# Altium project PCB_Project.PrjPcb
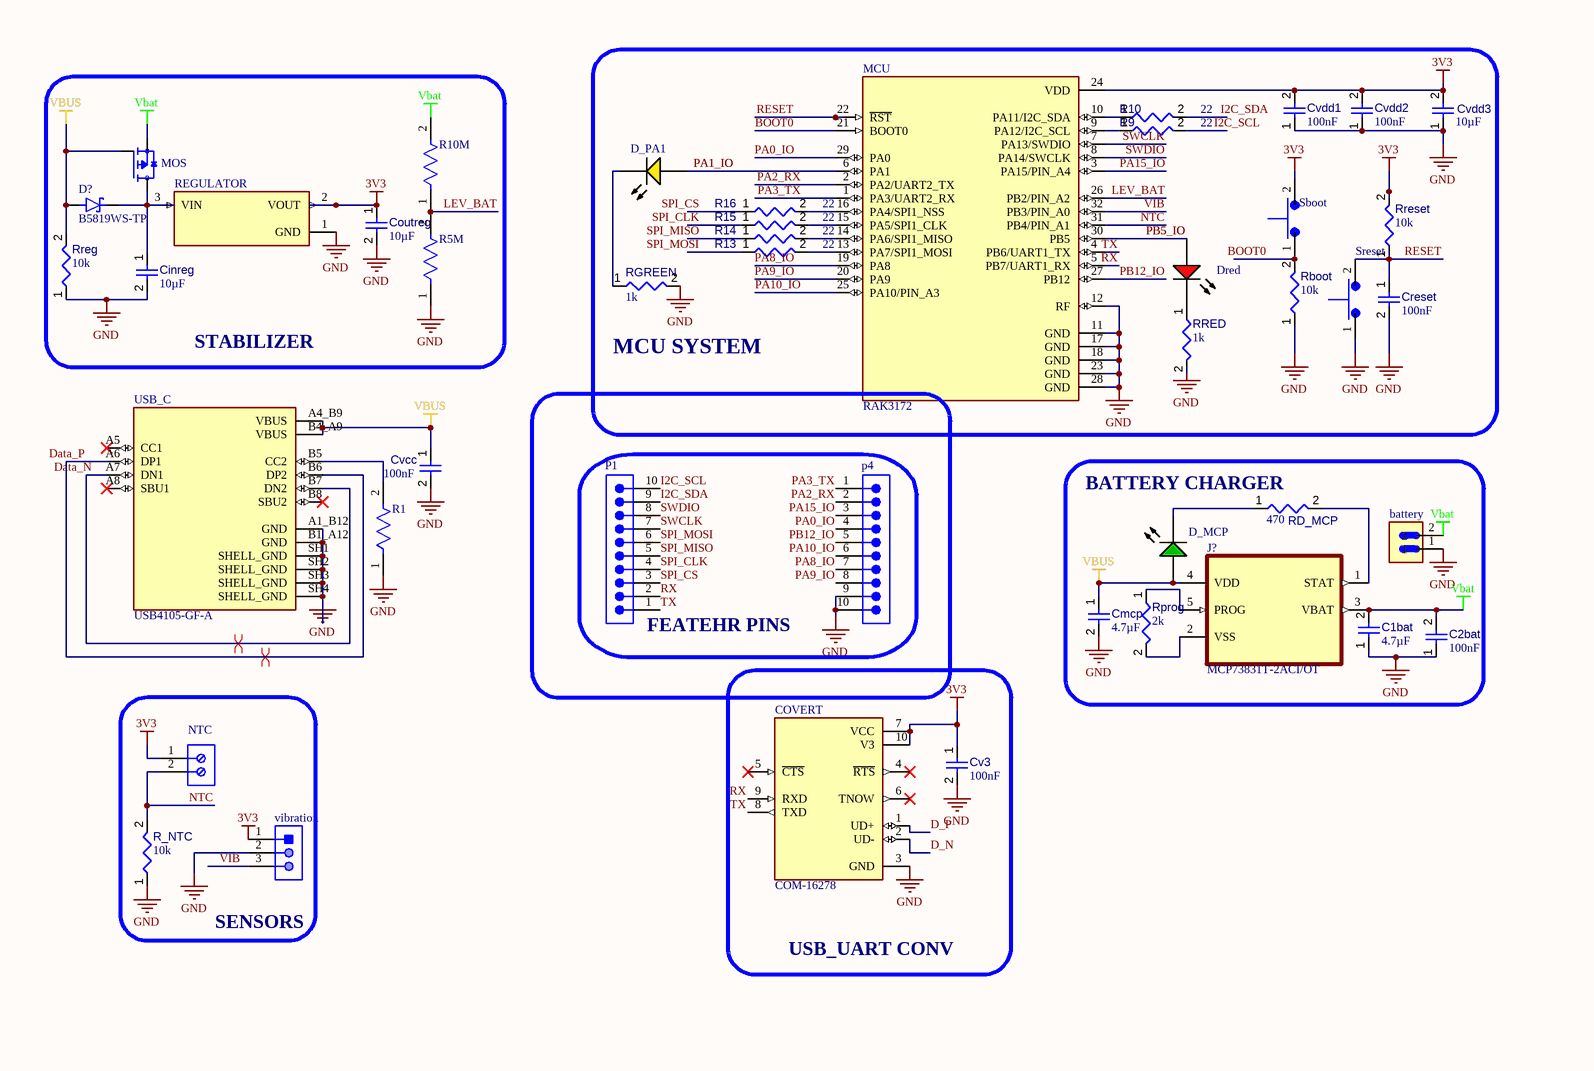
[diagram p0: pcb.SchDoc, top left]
1 sheet, 45 parts. Net scope: global (net labels, ports and power ports of the same name join across sheets).
Board files: PCB1.PcbDoc, PCB2.PcbDoc

## Sheet pcb.SchDoc
size A4; SheetNumber: 1; SheetTotal: 1

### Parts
battery  (no value)  [JST_S2B-PH-SM4-TB]
C1bat  value 4.7µF  [CAPC0805(2012)145_L]  (hidden comment: Capacitor 4.7µF +/-40% 25V 0805)
C2bat  value 100nF  [CAPC2013X95X50LL10T25]  (hidden comment: Capacitor 100 nF +/-10% 50 V 0805)
Cinreg  value 10µF  [CAPC0805(2012)145_L]  (hidden comment: Capacitor 10µF +/-20% 25V 0805)
Cmcp  value 4.7µF  [CAPC0805(2012)145_L]  (hidden comment: Capacitor 4.7µF +/-40% 25V 0805)
Coutreg  value 10µF  [CAPC0805(2012)145_L]  (hidden comment: Capacitor 10µF +/-20% 25V 0805)
COVERT  COM-16278  [SOP50P490X120-10N]
Creset  value 100nF  [CAPC2013X95X50LL10T25]  (hidden comment: Capacitor 100 nF +/-10% 50 V 0805)
Cv3  value 100nF  [CAPC2013X95X50LL10T25]  (hidden comment: Capacitor 100 nF +/-10% 50 V 0805)
Cvcc  value 100nF  [CAPC2013X95X50LL10T25]  (hidden comment: Capacitor 100 nF +/-10% 50 V 0805)
Cvdd1  value 100nF  [CAPC2013X95X50LL10T25]  (hidden comment: Capacitor 100 nF +/-10% 50 V 0805)
Cvdd2  value 100nF  [CAPC2013X95X50LL10T25]  (hidden comment: Capacitor 100 nF +/-10% 50 V 0805)
Cvdd3  value 10µF  [CAPC0805(2012)145_L]  (hidden comment: Capacitor 10µF +/-20% 25V 0805)
D?  B5819WS-TP  [SOD2512X115N]
D_MCP  (no value)  [LTST-C190GKT_V]
D_PA1  (no value)  [AVAG-HSMX-C190_V]
Dred  (no value)  [AVAG-HSMX-C190_V]
J?  MCP73831T-2ACI/OT  [SOT95P280X145-5N]
MCU  RAK3172  [XCVR_RAK3172-8-SM-NI]
MOS  (no value)  [TRANS_TSM500P02CX]
NTC  (no value)  [691213710002]
P1  (no value)  [61301011121]
p4  (no value)  [61301011121]
R1  (no value)  [FP-CRCW0805-e3-MFG]
R5M  (no value)  [FP-WSLP0805-MFG]
R9  value 22  [RESC0402(1005)_L]  (hidden comment: Resistor 22R  +/-5 % 0402 63 mW)
R10  value 22  [RESC0402(1005)_L]  (hidden comment: Resistor 22R  +/-5 % 0402 63 mW)
R10M  (no value)  [FP-CRCW0603-e3-IPC_A]
R13  value 22  [RESC0402(1005)_L]  (hidden comment: Resistor 22R  +/-5 % 0402 63 mW)
R14  value 22  [RESC0402(1005)_L]  (hidden comment: Resistor 22R  +/-5 % 0402 63 mW)
R15  value 22  [RESC0402(1005)_L]  (hidden comment: Resistor 22R  +/-5 % 0402 63 mW)
R16  value 22  [RESC0402(1005)_L]  (hidden comment: Resistor 22R  +/-5 % 0402 63 mW)
R_NTC  value 10k  [RESC0402(1005)_L]  (hidden comment: 10KR2F)
Rboot  value 10k  [RESC1005X40X25ML05T05]  (hidden comment: Resistor 10k +/-1% 0402 63 mW)
RD_MCP  value 470  [RESC0805(2012)_L]  (hidden comment: Resistor 470R +/-5% 0805 125 mW)
REGULATOR  (no value)  [SOT95P237X112-3N]
RGREEN  value 1k  [RESC0805(2012)_L]  (hidden comment: 1KR5J)
Rprog  value 2k  [RESC0402(1005)_L]  (hidden comment: 2KR2J)
RRED  value 1k  [RESC0805(2012)_L]  (hidden comment: 1KR5J)
Rreg  value 10k  [RESC0402(1005)_L]  (hidden comment: 10KR2F)
Rreset  value 10k  [RESC1005X40X25ML05T05]  (hidden comment: Resistor 10k +/-1% 0402 63 mW)
Sboot  (no value)  [SW_TS10-63-26-BE-250-SMT-TR]
Sreset  (no value)  [SW_TS10-63-26-BE-250-SMT-TR]
USB_C  USB4105-GF-A  [GCT_USB4105-GF-A]
vibration  (no value)  [MOLX-22-28-4033_V]

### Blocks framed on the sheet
STABILIZER: Cinreg Coutreg D? MOS R5M R10M REGULATOR Rreg
MCU SYSTEM: Creset Cvdd1-Cvdd3 D_PA1 Dred MCU R9 R10 R13-R16 Rboot RGREEN RRED Rreset Sboot Sreset
FEATEHR PINS: P1 p4
BATTERY CHARGER: battery C1bat C2bat Cmcp D_MCP J? RD_MCP Rprog
USB_UART CONV: COVERT Cv3
SENSORS: NTC R_NTC vibration

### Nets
3V3: Coutreg.1 COVERT.7(VCC) COVERT.10(V3) Cv3.1 Cvdd1.2 Cvdd2.2 Cvdd3.2 MCU.24(VDD) NTC.1 REGULATOR.2(VOUT) Rreset.2 Sboot.2 vibration.1
GND: battery.1 C1bat.1 C2bat.1 Cinreg.2 Cmcp.2 Coutreg.2 COVERT.3(GND) Creset.2 Cv3.2 Cvcc.2 Cvdd1.1 Cvdd2.1 Cvdd3.1 MCU.11(GND) MCU.12(RF) MCU.17(GND) MCU.18(GND) MCU.23(GND) MCU.28(GND) p4.9 p4.10 R1.1 R5M.1 R_NTC.1 Rboot.1 REGULATOR.1(GND) RGREEN.2 RRED.2 Rreg.1 Sreset.1 USB_C.A1_B12(GND) USB_C.B1_A12(GND) USB_C.SH1(SHELL_GND) USB_C.SH2(SHELL_GND) USB_C.SH3(SHELL_GND) USB_C.SH4(SHELL_GND) vibration.2
Vbat: battery.2 C1bat.2 C2bat.2 J?.3(VBAT) MOS.2(S) R10M.2
VBUS: Cmcp.1 Cvcc.1 D?.A D_MCP.1(A) J?.4(VDD) MOS.1(G) Rreg.2 USB_C.A4_B9(VBUS) USB_C.B4_A9(VBUS)
BOOT0: MCU.21(BOOT0) Rboot.2 Sboot.1
D_N: COVERT.2(UD-)
D_P: COVERT.1(UD+)
Data_N: USB_C.A7(DN1) USB_C.B7(DN2)
Data_P: USB_C.A6(DP1) USB_C.B6(DP2)
I2C_SCL: P1.10 R9.2
I2C_SDA: P1.9 R10.2
LEV_BAT: MCU.26(PB2/PIN_A2) R5M.2 R10M.1
NTC: MCU.31(PB4/PIN_A1) NTC.2 R_NTC.2
PA0_IO: MCU.29(PA0) p4.4
PA1_IO: D_PA1.1(A) MCU.6(PA1)
PA2_RX: MCU.2(PA2/UART2_TX) p4.2
PA3_TX: MCU.1(PA3/UART2_RX) p4.1
PA8_IO: MCU.19(PA8) p4.7
PA9_IO: MCU.20(PA9) p4.8
PA10_IO: MCU.25(PA10/PIN_A3) p4.6
PA15_IO: MCU.3(PA15/PIN_A4) p4.3
PB5_IO: Dred.1(A) MCU.30(PB5)
PB12_IO: MCU.27(PB12) p4.5
RESET: Creset.1 MCU.22(~{RST}) Rreset.1 Sreset.2
RX: COVERT.9(RXD) MCU.5(PB7/UART1_RX) P1.2
SPI_CLK: P1.4 R16.1
SPI_CS: P1.3 R15.1
SPI_MISO: P1.5 R14.1
SPI_MOSI: P1.6 R13.1
SWCLK: MCU.7(PA13/SWDIO) P1.7
SWDIO: MCU.8(PA14/SWCLK) P1.8
TX: COVERT.8(TXD) MCU.4(PB6/UART1_TX) P1.1
VIB: MCU.32(PB3/PIN_A0) vibration.3
NetCinreg_1: Cinreg.1 D?.C(K) MOS.3(D) REGULATOR.3(VIN)
NetD_MCP_2: D_MCP.2(K) RD_MCP.1
NetD_PA1_2: D_PA1.2(K) RGREEN.1
NetDred_2: Dred.2(K) RRED.1
NetJ?_1: J?.1(STAT) RD_MCP.2
NetJ?_2: J?.2(VSS) Rprog.2
NetJ?_5: J?.5(PROG) Rprog.1
NetMCU_9: MCU.9(PA12/I2C_SCL) R9.1
NetMCU_10: MCU.10(PA11/I2C_SDA) R10.1
NetMCU_13: MCU.13(PA7/SPI1_MOSI) R13.2
NetMCU_14: MCU.14(PA6/SPI1_MISO) R14.2
NetMCU_15: MCU.15(PA5/SPI1_CLK) R16.2
NetMCU_16: MCU.16(PA4/SPI1_NSS) R15.2
NetR1_2: R1.2 USB_C.B5(CC2)

Not connected (* = marked no-connect by the designer): COVERT 4(~{RTS})* 5(~{CTS})* 6(TNOW)*; USB_C A5(CC1)* A8(SBU1)* B8(SBU2)*

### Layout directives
differential pair: Data_N, Data_P

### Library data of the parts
battery = S2B-PH-SM4-TB: Connector Header Surface Mount, Right Angle 2 position 0.079 (2.00mm); MF: JST Sales
C1bat Cmcp = CMP-001-00080-4: Chip Capacitor, 4.7µF +/-40%, 25V, 0805, Thickness 1.45 mm; Tolerance: 20%
C2bat Creset Cv3 Cvcc Cvdd1 Cvdd2 = CMP-001-00018-6: Chip Capacitor, 100 nF, +/- 10%, 50 V, 0805 (2012 Metric); Capacitor Type: Ceramic; Voltage Rating: 50V
Cinreg Coutreg Cvdd3 = CMP-001-00079-4: Chip Capacitor, 10µF +/-20%, 25V, 0805, Thickness 1.45 mm; Tolerance: 10%
COVERT = COM-16278: SparkFun Accessories USB to Serial IC - CH340E (10 Pack)
D? = B5819WS-TP: Diode Schottky 40 V 1A Surface Mount SOD-323; MF: Micro Commercial
D_MCP = CMP-007-00022-2: LED Uni-Color Green, 100 mW, 30 mA, -55 to 85 degC, 2-Pin SMD, RoHS, Tape and Reel; Manufacturer: Lite-On; Power: 100mW; Forward Voltage: 2.1V; Viewing Angle: 130degrees; Forward Current: 20mA; Luminous Intensity: 6mcd; Lens Style: Clear
D_PA1 = CMP-007-00017-2: LED Uni-Color Yellow, 65 mW, 20 mA, -40 to 85 degC, 2-Pin SMD, RoHS, Tape and Reel; Manufacturer: Avago; Forward Current: 20mA; Viewing Angle: 170degrees; Power: 52mW; Lens Style: Diffused; Nominal Vf: 2.1V; Luminous Intensity: 8mcd
Dred = CMP-007-00014-2: LED Uni-Color Red, 65 mW, 20 mA, -40 to 85 degC, 2-Pin SMD, RoHS, Tape and Reel; Manufacturer: Avago; Nominal Vf: 1.8V; Luminous Intensity: 17mcd; Power: 78mW; Forward Current: 20mA; Lens Style: Diffused; Viewing Angle: 170degrees
J? = MCP73831T-2ACI/OT: Charger IC Lithium Ion/Polymer SOT-23-5; MF: Microchip
MCU = RAK3172-8-SM-NI: RF IC Transceiver LoRaWAN 864MHz, 865MHz, 868MHz 2V ~ 3.6V Supply, Without IPEX Connector; MF: RAKwireless Technology Limited
MOS = TSM500P02CX: P-Channel 20 V 4.7A (Tc) 1.56W (Tc) Surface Mount SOT-23; MF: Taiwan Semiconductor
NTC = CMP-1502-02526-2: NexarPartId: 8917718; Number of Contacts: 2; Current Rating: 10A; Stripping Length: -7mm; Wire Gauge (Max): 26AWG; Plating: Brass, Steel; Wire Gauge (Min): 16AWG; Voltage: 300V; Number of Levels: 1; Pitch: 5.0038mm
P1 p4 = CMP-1502-01082-5: NexarPartId: 18818159; Gender: Male; Number of Positions: 10; Operating Supply Voltage: 250V; Current Rating: 3A; Contact Resistance: 20mΩ; Connector Type: Male Pin; Insulation Resistance: 1GΩ; Pitch: 2.54mm
R1 = CMP-2001-04024-2: RES Thick Film, 5.1kΩ, 1%, 0.125W, 100ppm/°C, 0805; Power Rating: 125mW; Voltage Rating (DC): 150V; Resistance: 5.1kR
R5M = CMP-02407-013125-1: RES 0.005 OHM 1% 1W 0805; Resistance: 5mR; Temperature Coefficient: 110ppm/°C
R9 R10 R13-R16 = CMP-009-00164-3: Chip Resistor, 22 Ohms, +/-5 %, 63 mW, -55 to 155 degC, 0402; Tolerance: 5%; Power: 63mW
R10M = CMP-2000-03844-2: RES Thick Film, 10MΩ, 5%, 0.1W, 200ppm/°C, 0603; Power Rating: 100mW; Voltage Rating: 75V; Resistance: 10MR
R_NTC Rreg = CMP-009-00066-2: 10K 0.063W 1% 0402 (1005 Metric)  SMD; Power: 63mW
Rboot Rreset = CMP-009-00019-5: Chip Resistor, 10 KOhm, +/- 1%, 63 mW, -55 to 155 degC, 0402 (1005 Metric); Power: 63mW; Voltage Rating: 50V
RD_MCP = CMP-009-00122-3: Chip Resistor, 470 Ohms, +/-5%, 125 mW, -55 to 155 degC, 0805; Tolerance: 5%; Power: 125mW
REGULATOR = MCP1700T-3302E_TT: Pwr Sply Func,Voltage Regulator,LDO,SOT-23,PD 369.6mW,VO 3.3V,Regline +/-0.75%/V ¦ Microchip Technology Inc. MCP1700T-3302E/TT
RGREEN RRED = CMP-009-00076-2: 1K 0.125W 5% 0805 (2012 Metric)  SMD; Power: 125mW
Rprog = CMP-009-00091-2: 2K 0.063W 5% 0402 (1005 Metric)  SMD; Power: 63mW
Sboot Sreset = TS10-63-26-BE-250-SMT-TR: 6.1 x 3.8 mm, 2.6 mm Actuator Height, 250 gf, Surface Mount, SPST, Tactile Switch; MF: Same Sky
USB_C = USB4105-GF-A: MF: {'manufacturer': u'GCT'}
vibration = CMP-1676-00001-5: Male Header, Pitch 2.54 mm, 1 x 3 Position, Height 8.38 mm, Tail Length 3.18 mm, RoHS, Bulk; Manufacturer: Molex; Rows: 1; Voltage Rating: 250 V; Current Rating: 4 A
